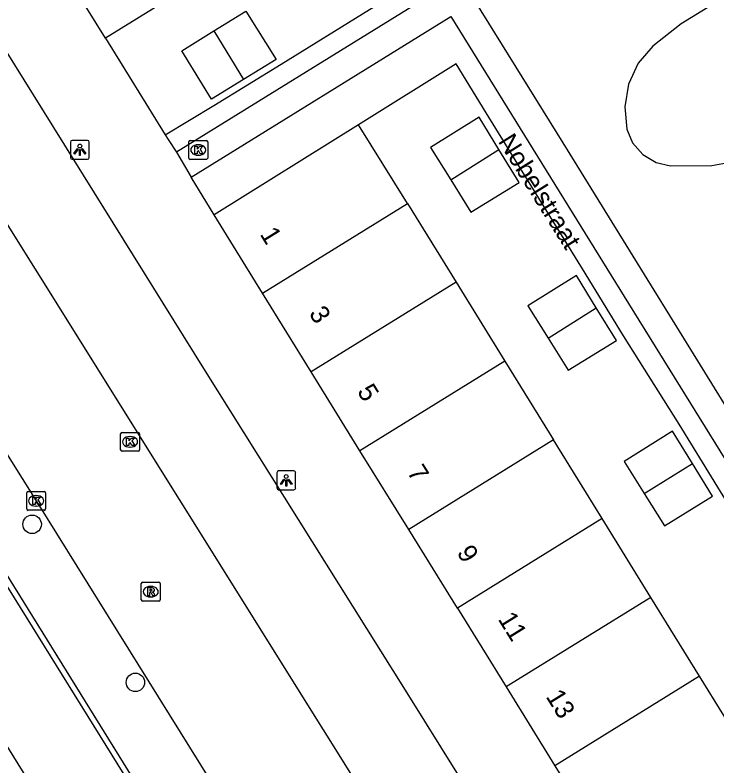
# Model space of a CAD drawing. Extents: x 159888 to 160757, y 384031 to 384746.
# Drawn here: x 160123.93 to 160161.08, y 384520.33 to 384560.06 of the extents above; entities that cross this region are included whole.
import ezdxf

# ---------------------------------------------------------------- set-up
doc = ezdxf.new("R2010")
doc.units = 0
for name, color, linetype in [('IMGEO_Boom', 7, 'Continuous'), ('IMGEO_Groenvoorziening', 7, 'Continuous'), ('IMGEO_Kolk', 7, 'Continuous'), ('IMGEO_Lichtpunt', 7, 'Continuous'), ('IMGEO_Openbare_ruimte_label', 7, 'Continuous'), ('IMGEO_Pand', 7, 'Continuous'), ('IMGEO_Pand_nummerreeks', 7, 'Continuous'), ('IMGEO_Parkeervlak_open', 7, 'Continuous'), ('IMGEO_Rijbaan_lokaal_open', 7, 'Continuous'), ('IMGEO_Rioolput', 7, 'Continuous'), ('IMGEO_Voetpad_open', 7, 'Continuous')]:
    doc.layers.add(name, color=color, linetype=linetype)

msp = doc.modelspace()

# ---------------------------------------------------------------- linework, layer by layer
at = {"layer": 'IMGEO_Boom'}
for centre in [(160124.834, 384533.118), (160130.298, 384524.756)]:
    msp.add_circle(centre, 0.489, dxfattribs=at)
at = {"layer": 'IMGEO_Groenvoorziening'}
for points in [[(160131.882, 384553.717), (160134.451, 384555.279), (160138.005, 384557.454), (160142.688, 384560.346), (160146.234, 384562.542), (160150.964, 384565.459), (160154.504, 384567.651), (160159.181, 384570.545), (160162.717, 384572.729), (160167.402, 384575.62), (160170.932, 384577.817), (160175.649, 384580.721), (160176.59, 384581.308), (160177.945, 384582.154), (160178.648, 384582.593)], [(160160.832, 384560.601), (160159.184, 384559.601), (160157.679, 384558.409), (160156.914, 384557.513), (160156.396, 384556.407), (160156.195, 384555.201), (160156.316, 384554.03), (160156.614, 384553.304), (160157.149, 384552.677), (160157.857, 384552.252), (160158.621, 384552.079), (160160.802, 384552.108), (160162.949, 384552.494), (160164.227, 384552.975), (160165.406, 384553.716), (160166.412, 384554.681), (160167.187, 384555.805), (160167.398, 384556.377), (160167.429, 384556.987)], [(160170.433, 384519.911), (160169.216, 384521.94), (160166.364, 384526.593), (160164.187, 384530.138), (160161.258, 384534.862), (160159.072, 384538.41), (160156.136, 384543.082), (160153.968, 384546.63), (160151.058, 384551.349), (160148.865, 384554.895), (160147.274, 384557.486), (160142.113, 384554.255)]]:
    msp.add_lwpolyline(points, dxfattribs=at)
at = {"layer": 'IMGEO_Kolk'}
for p, q in [((160133.126, 384552.497), (160133.126, 384553.349)), ((160133.201, 384553.423), (160134.053, 384553.423)), ((160133.614, 384553.203), (160133.639, 384553.203)), ((160134.127, 384553.349), (160134.127, 384552.497)), ((160134.053, 384552.423), (160133.201, 384552.423)), ((160133.637, 384552.643), (160133.612, 384552.643)), ((160129.515, 384537.055), (160129.515, 384537.907)), ((160129.59, 384537.981), (160130.442, 384537.981)), ((160130.003, 384537.761), (160130.028, 384537.761)), ((160130.516, 384537.907), (160130.516, 384537.055)), ((160130.442, 384536.981), (160129.59, 384536.981)), ((160130.026, 384537.201), (160130.001, 384537.201)), ((160124.546, 384533.932), (160124.546, 384534.784)), ((160124.621, 384534.858), (160125.473, 384534.858)), ((160125.034, 384534.638), (160125.059, 384534.638)), ((160125.547, 384534.784), (160125.547, 384533.932)), ((160125.473, 384533.858), (160124.621, 384533.858)), ((160125.057, 384534.078), (160125.032, 384534.078))]:
    msp.add_line(p, q, dxfattribs=at)
for points in [[(160133.126, 384552.497), (160133.126, 384553.349)], [(160133.201, 384553.423), (160134.053, 384553.423)], [(160134.127, 384553.349), (160134.127, 384552.497)], [(160133.447, 384553.123), (160133.57, 384553.123), (160133.57, 384552.972), (160133.7, 384553.123), (160133.864, 384553.123), (160133.718, 384552.972), (160133.871, 384552.723), (160133.719, 384552.723), (160133.634, 384552.887), (160133.57, 384552.82), (160133.57, 384552.723), (160133.447, 384552.723), (160133.447, 384553.123)], [(160134.053, 384552.423), (160133.201, 384552.423)], [(160129.515, 384537.055), (160129.515, 384537.907)], [(160129.59, 384537.981), (160130.442, 384537.981)], [(160129.836, 384537.681), (160129.959, 384537.681), (160129.959, 384537.53), (160130.089, 384537.681), (160130.253, 384537.681), (160130.107, 384537.53), (160130.26, 384537.281), (160130.108, 384537.281), (160130.023, 384537.445), (160129.959, 384537.378), (160129.959, 384537.281), (160129.836, 384537.281), (160129.836, 384537.681)], [(160130.516, 384537.907), (160130.516, 384537.055)], [(160130.442, 384536.981), (160129.59, 384536.981)], [(160124.546, 384533.932), (160124.546, 384534.784)], [(160124.621, 384534.858), (160125.473, 384534.858)], [(160124.867, 384534.558), (160124.99, 384534.558), (160124.99, 384534.407), (160125.12, 384534.558), (160125.284, 384534.558), (160125.138, 384534.407), (160125.291, 384534.158), (160125.139, 384534.158), (160125.054, 384534.322), (160124.99, 384534.255), (160124.99, 384534.158), (160124.867, 384534.158), (160124.867, 384534.558)], [(160125.547, 384534.784), (160125.547, 384533.932)], [(160125.473, 384533.858), (160124.621, 384533.858)]]:
    msp.add_lwpolyline(points, dxfattribs=at)
for centre, start, end in [((160133.203, 384553.347), 91.552, 178.448), ((160133.203, 384553.347), 91.552, 178.448), ((160134.051, 384553.347), 1.552, 88.448), ((160134.051, 384553.347), 1.552, 88.448), ((160133.203, 384552.499), 181.552, 268.448), ((160133.203, 384552.499), 181.552, 268.448), ((160134.051, 384552.499), 271.552, 358.448), ((160134.051, 384552.499), 271.552, 358.448), ((160129.592, 384537.905), 91.552, 178.448), ((160129.592, 384537.905), 91.552, 178.448), ((160130.44, 384537.905), 1.552, 88.448), ((160130.44, 384537.905), 1.552, 88.448), ((160129.592, 384537.057), 181.552, 268.448), ((160129.592, 384537.057), 181.552, 268.448), ((160130.44, 384537.057), 271.552, 358.448), ((160130.44, 384537.057), 271.552, 358.448), ((160124.623, 384534.782), 91.552, 178.448), ((160124.623, 384534.782), 91.552, 178.448), ((160125.471, 384534.782), 1.552, 88.448), ((160125.471, 384534.782), 1.552, 88.448), ((160124.623, 384533.934), 181.552, 268.448), ((160124.623, 384533.934), 181.552, 268.448), ((160125.471, 384533.934), 271.552, 358.448), ((160125.471, 384533.934), 271.552, 358.448)]:
    msp.add_arc(centre, 0.0765, start, end, dxfattribs=at)
for centre, major_axis, ratio, start_param, end_param in [((160133.613, 384552.923), (-0.387, 0.002), 0.722429, 4.712389, 7.853982), ((160133.638, 384552.923), (-0.39, 0.002), 0.717154, 1.570796, 4.712389), ((160130.002, 384537.481), (-0.387, 0.002), 0.722429, 4.712389, 7.853982), ((160130.027, 384537.481), (-0.39, 0.002), 0.717154, 1.570796, 4.712389), ((160125.033, 384534.358), (-0.387, 0.002), 0.722429, 4.712389, 7.853982), ((160125.058, 384534.358), (-0.39, 0.002), 0.717154, 1.570796, 4.712389)]:
    msp.add_ellipse(centre, major_axis=major_axis, ratio=ratio, start_param=start_param, end_param=end_param, dxfattribs=at)
at = {"layer": 'IMGEO_Lichtpunt'}
for p, q in [((160126.859, 384553.333), (160126.859, 384552.526)), ((160126.859, 384553.333), (160126.859, 384552.526)), ((160127.761, 384553.428), (160126.953, 384553.428)), ((160127.761, 384553.428), (160126.953, 384553.428)), ((160127.855, 384552.526), (160127.855, 384553.333)), ((160127.855, 384552.526), (160127.855, 384553.333)), ((160126.953, 384552.432), (160127.761, 384552.432)), ((160126.953, 384552.432), (160127.761, 384552.432)), ((160137.784, 384535.848), (160137.784, 384535.041)), ((160137.784, 384535.848), (160137.784, 384535.041)), ((160138.686, 384535.943), (160137.878, 384535.943)), ((160138.686, 384535.943), (160137.878, 384535.943)), ((160138.78, 384535.041), (160138.78, 384535.848)), ((160138.78, 384535.041), (160138.78, 384535.848)), ((160137.878, 384534.947), (160138.686, 384534.947)), ((160137.878, 384534.947), (160138.686, 384534.947))]:
    msp.add_line(p, q, dxfattribs=at)
for points in [[(160127.233, 384552.997), (160127.272, 384552.969), (160127.084, 384552.707), (160127.046, 384552.734), (160127.233, 384552.997)], [(160127.335, 384552.949), (160127.382, 384552.949), (160127.382, 384552.627), (160127.335, 384552.627), (160127.335, 384552.949)], [(160127.445, 384552.969), (160127.483, 384552.996), (160127.67, 384552.734), (160127.631, 384552.706), (160127.445, 384552.969)], [(160138.158, 384535.512), (160138.197, 384535.484), (160138.009, 384535.222), (160137.971, 384535.249), (160138.158, 384535.512)], [(160138.26, 384535.464), (160138.307, 384535.464), (160138.307, 384535.142), (160138.26, 384535.142), (160138.26, 384535.464)], [(160138.37, 384535.484), (160138.408, 384535.511), (160138.595, 384535.249), (160138.556, 384535.221), (160138.37, 384535.484)]]:
    msp.add_lwpolyline(points, dxfattribs=at)
for centre in [(160127.358, 384553.131), (160138.283, 384535.646)]:
    msp.add_circle(centre, 0.0994, dxfattribs=at)
for centre, start, end in [((160126.953, 384553.333), 90, 180), ((160126.953, 384553.333), 90, 180), ((160127.761, 384553.333), 0, 90), ((160127.761, 384553.333), 0, 90), ((160126.953, 384552.526), 180, 270), ((160126.953, 384552.526), 180, 270), ((160127.761, 384552.526), 270, 0), ((160127.761, 384552.526), 270, 360), ((160137.878, 384535.848), 90, 180), ((160137.878, 384535.848), 90, 180), ((160138.686, 384535.848), 0, 90), ((160138.686, 384535.848), 0, 90), ((160137.878, 384535.041), 180, 270), ((160137.878, 384535.041), 180, 270), ((160138.686, 384535.041), 270, 0), ((160138.686, 384535.041), 270, 360)]:
    msp.add_arc(centre, 0.0946, start, end, dxfattribs=at)
at = {"layer": 'IMGEO_Pand'}
for points in [[(160128.712, 384558.84), (160123.961, 384566.517), (160128.118, 384569.089)], [(160132.866, 384561.408), (160128.712, 384558.84)], [(160134.453, 384559.217), (160136.15, 384560.257), (160137.747, 384557.71), (160136.022, 384556.655)], [(160136.022, 384556.655), (160134.322, 384555.615), (160132.755, 384558.176), (160134.453, 384559.217)], [(160134.453, 384559.217), (160136.022, 384556.655)], [(160149.54, 384552.943), (160148.491, 384554.654), (160145.918, 384553.048), (160146.988, 384551.343)], [(160142.113, 384554.255), (160134.463, 384549.497)], [(160144.691, 384550.087), (160142.113, 384554.255)], [(160146.988, 384551.343), (160149.54, 384552.943)], [(160146.988, 384551.343), (160148.057, 384549.637), (160150.604, 384551.208), (160149.54, 384552.943)], [(160137.029, 384545.349), (160144.691, 384550.087)], [(160144.691, 384550.087), (160147.268, 384545.92)], [(160137.029, 384545.349), (160134.463, 384549.497)], [(160154.69, 384544.572), (160153.641, 384546.283), (160151.068, 384544.677), (160152.137, 384542.972)], [(160147.268, 384545.92), (160139.607, 384541.181)], [(160147.268, 384545.92), (160149.846, 384541.752)], [(160139.607, 384541.181), (160137.029, 384545.349)], [(160152.137, 384542.972), (160154.69, 384544.572)], [(160152.137, 384542.972), (160153.207, 384541.266), (160155.754, 384542.837), (160154.69, 384544.572)], [(160149.846, 384541.752), (160142.185, 384537.014)], [(160149.846, 384541.752), (160152.424, 384537.585)], [(160142.185, 384537.014), (160139.607, 384541.181)], [(160159.78, 384536.34), (160158.731, 384538.051), (160156.158, 384536.445), (160157.227, 384534.74)], [(160152.424, 384537.585), (160144.763, 384532.847)], [(160155.001, 384533.417), (160152.424, 384537.585)], [(160144.763, 384532.847), (160142.185, 384537.014)], [(160157.227, 384534.74), (160159.78, 384536.34)], [(160157.227, 384534.74), (160158.297, 384533.034), (160160.844, 384534.605), (160159.78, 384536.34)], [(160155.001, 384533.417), (160147.341, 384528.679)], [(160157.579, 384529.25), (160155.001, 384533.417)], [(160147.341, 384528.679), (160144.763, 384532.847)], [(160157.579, 384529.25), (160149.919, 384524.512)], [(160160.157, 384525.082), (160157.579, 384529.25)], [(160147.341, 384528.679), (160149.919, 384524.512)], [(160160.157, 384525.082), (160152.497, 384520.345)], [(160162.734, 384520.915), (160160.157, 384525.082)], [(160149.919, 384524.512), (160152.497, 384520.345)], [(160152.497, 384520.345), (160155.075, 384516.177)]]:
    msp.add_lwpolyline(points, dxfattribs=at)
at = {"layer": 'IMGEO_Parkeervlak_open'}
msp.add_lwpolyline([(160113.651, 384544.027), (160114.383, 384544.49), (160140.747, 384502.072), (160137.467, 384500), (160136.964, 384499.682)], dxfattribs=at)
at = {"layer": 'IMGEO_Rijbaan_lokaal_open'}
for points in [[(160102.306, 384570.763), (160113.563, 384552.653), (160125.049, 384534.359), (160139.118, 384511.747), (160144.747, 384502.719)], [(160147.868, 384510.063), (160117.379, 384558.808)], [(160136.964, 384499.682), (160136.767, 384500), (160133.491, 384505.278), (160125.564, 384518.085), (160117.707, 384530.736), (160110.676, 384542.144)]]:
    msp.add_lwpolyline(points, dxfattribs=at)
at = {"layer": 'IMGEO_Rioolput'}
for p, q in [((160130.608, 384529.128), (160130.608, 384529.98)), ((160130.683, 384530.054), (160131.535, 384530.054)), ((160131.096, 384529.834), (160131.121, 384529.834)), ((160131.609, 384529.98), (160131.609, 384529.128)), ((160131.535, 384529.054), (160130.683, 384529.054)), ((160131.119, 384529.274), (160131.094, 384529.274))]:
    msp.add_line(p, q, dxfattribs=at)
for points in [[(160130.608, 384529.128), (160130.608, 384529.98)], [(160130.683, 384530.054), (160131.535, 384530.054)], [(160131.197, 384529.752), (160130.945, 384529.754), (160130.945, 384529.354)], [(160131.609, 384529.98), (160131.609, 384529.128)], [(160130.945, 384529.354), (160131.069, 384529.354), (160131.069, 384529.516), (160131.08, 384529.516)], [(160131.123, 384529.673), (160131.069, 384529.673), (160131.069, 384529.592)], [(160131.069, 384529.592), (160131.121, 384529.592)], [(160131.127, 384529.487), (160131.198, 384529.354), (160131.338, 384529.354), (160131.273, 384529.48)], [(160131.535, 384529.054), (160130.683, 384529.054)]]:
    msp.add_lwpolyline(points, dxfattribs=at)
for centre, radius, start, end in [((160130.685, 384529.978), 0.0765, 91.552, 178.448), ((160130.685, 384529.978), 0.0765, 91.552, 178.448), ((160131.196, 384529.642), 0.109, 350.3612, 89.416), ((160131.533, 384529.978), 0.0765, 1.552, 88.448), ((160131.533, 384529.978), 0.0765, 1.552, 88.448), ((160131.079, 384529.463), 0.0533, 26.0293, 88.6989), ((160131.105, 384529.781), 0.19, 274.7715, 282.9687), ((160131.129, 384529.577), 0.0964, 77.0061, 93.1865), ((160131.143, 384529.634), 0.0378, 276.6634, 79.6772), ((160131.194, 384529.642), 0.112, 277.5842, 350.9817), ((160131.178, 384529.427), 0.108, 29.5134, 73.7905), ((160130.685, 384529.13), 0.0765, 181.552, 268.448), ((160130.685, 384529.13), 0.0765, 181.552, 268.448), ((160131.533, 384529.13), 0.0765, 271.552, 358.448), ((160131.533, 384529.13), 0.0765, 271.552, 358.448)]:
    msp.add_arc(centre, radius, start, end, dxfattribs=at)
for centre, major_axis, ratio, start_param, end_param in [((160131.095, 384529.554), (-0.387, 0.002), 0.722429, 4.712389, 7.853982), ((160131.12, 384529.554), (-0.39, 0.002), 0.717154, 1.570796, 4.712389)]:
    msp.add_ellipse(centre, major_axis=major_axis, ratio=ratio, start_param=start_param, end_param=end_param, dxfattribs=at)
at = {"layer": 'IMGEO_Voetpad_open'}
for points in [[(160200.868, 384559.503), (160163.406, 384536.375), (160152.94, 384553.3), (160148.281, 384560.789), (160181.266, 384581.183), (160180.644, 384582.188), (160185.149, 384585.056), (160186.066, 384583.561), (160189.322, 384578.257), (160196.17, 384567.098), (160200.122, 384560.709)], [(160178.648, 384582.593), (160179.214, 384581.669), (160139.949, 384557.419), (160132.473, 384552.799)], [(160117.97, 384558.646), (160119.572, 384559.594), (160121.735, 384560.901), (160133.91, 384541.367), (160144.66, 384524.211), (160151.885, 384512.636), (160147.868, 384510.063)], [(160133.251, 384551.488), (160147, 384559.992), (160156.159, 384545.179), (160169.806, 384523.173), (160171.445, 384520.533)], [(160128.712, 384558.84), (160131.882, 384553.717)], [(160131.882, 384553.717), (160132.027, 384553.482), (160132.473, 384552.799)], [(160132.473, 384552.799), (160133.251, 384551.488)], [(160134.463, 384549.497), (160133.251, 384551.488)], [(160141.73, 384501.039), (160111.559, 384549.71)]]:
    msp.add_lwpolyline(points, dxfattribs=at)

# ---------------------------------------------------------------- texts
at = {"layer": 'IMGEO_Openbare_ruimte_label'}
msp.add_text('Nobelstraat', height=1, rotation=302.0054, dxfattribs=at).set_placement((160149.464, 384553.381))
at = {"layer": 'IMGEO_Pand_nummerreeks'}
for s, p in [('1', (160136.863, 384548.468)), ('3', (160139.455, 384544.277)), ('5', (160142.007, 384540.151)), ('7', (160144.649, 384535.881)), ('9', (160147.281, 384531.627)), ('11', (160149.46, 384528.106)), ('13', (160151.994, 384524.008))]:
    msp.add_text(s, height=1, rotation=301.7417, dxfattribs=at).set_placement(p)

doc.saveas('drawing.dxf')
